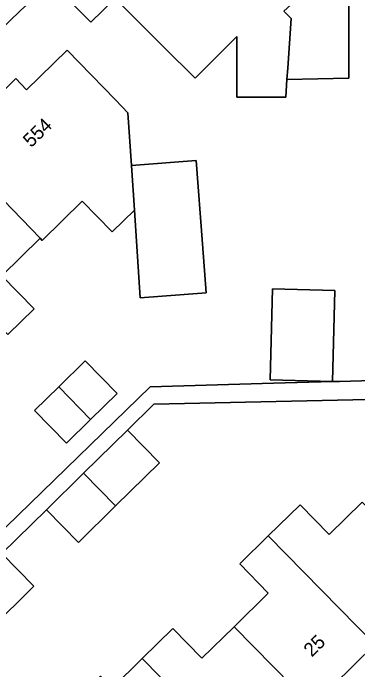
# Model space of a CAD drawing. Extents: x 162879 to 165540, y 384011 to 385181.
# Drawn here: x 164054.11 to 164079.05, y 384263.93 to 384311.42 of the extents above; entities that cross this region are included whole.
import ezdxf

# ---------------------------------------------------------------- set-up
doc = ezdxf.new("R2010")
doc.units = 0
for name, color, linetype in [('IMGEO_Erf', 7, 'Continuous'), ('IMGEO_Pand', 7, 'Continuous'), ('IMGEO_Pand_nummerreeks', 7, 'Continuous'), ('IMGEO_Voetpad_open', 7, 'Continuous')]:
    doc.layers.add(name, color=color, linetype=linetype)

msp = doc.modelspace()

# ---------------------------------------------------------------- linework, layer by layer
at = {"layer": 'IMGEO_Erf'}
for points in [[(164078.387, 384313.294), (164078.385, 384307.543), (164078.389, 384306.718), (164073.916, 384306.62), (164073.826, 384305.337), (164072.928, 384305.337), (164070.298, 384305.337), (164070.298, 384309.736), (164067.267, 384306.705), (164065.014, 384308.959), (164061.479, 384312.495), (164059.742, 384310.757), (164056.873, 384313.629)], [(164054.659, 384311.633), (164016.589, 384274.641), (164013.705, 384271.839), (164009.873, 384268.115), (164006.301, 384264.46), (164004.769, 384262.989), (164003.136, 384261.267), (164000.53, 384258.712), (164000.421, 384258.798), (164000, 384258.382), (163993.563, 384252.019), (163991.6, 384250), (163967.269, 384225.92)], [(164052.538, 384304.98), (164054.294, 384306.679), (164055.073, 384305.874), (164058.017, 384308.737), (164061.503, 384305.153), (164062.417, 384304.214), (164062.668, 384300.404), (164067.351, 384300.763), (164067.808, 384294.74), (164068.077, 384291.199), (164063.297, 384290.837), (164062.88, 384297.173), (164061.285, 384295.608), (164059.114, 384297.821), (164056.217, 384294.98), (164056.064, 384295.138), (164053.299, 384292.425), (164055.631, 384290.048), (164053.725, 384288.178)], [(164020.603, 384237.498), (164023.148, 384240.006), (164027.381, 384235.712), (164031.164, 384239.4), (164026.942, 384243.693), (164023.489, 384247.252), (164025.948, 384249.671), (164026.282, 384250), (164027.143, 384250.847), (164027.965, 384250), (164030.611, 384247.272), (164031.931, 384248.559), (164033.408, 384250), (164034.426, 384250.993), (164036.921, 384253.427), (164041.22, 384257.622), (164037.748, 384261.17), (164040.249, 384263.618), (164041.4, 384262.442), (164064.027, 384284.392), (164072.952, 384284.662), (164077.211, 384284.78), (164077.726, 384284.794), (164083.317, 384284.95)], [(164087.526, 384283.655), (164064.289, 384283.133), (164062.376, 384281.256), (164064.691, 384278.895), (164061.526, 384275.79), (164058.835, 384273.15), (164056.519, 384275.511), (164053.297, 384272.353), (164055.612, 384269.992), (164052.444, 384266.884), (164049.756, 384264.247), (164047.44, 384266.608), (164043.225, 384262.473)], [(164061.279, 384262.618), (164063.45, 384264.748), (164065.659, 384266.915), (164067.766, 384264.768), (164070.096, 384267.053), (164072.57, 384269.481), (164070.503, 384271.588), (164072.57, 384273.616), (164074.874, 384275.876), (164076.98, 384273.729), (164079.356, 384276.061)], [(164080.28, 384265.756), (164075.737, 384261.302), (164071.198, 384256.85), (164066.658, 384252.399), (164064.212, 384250), (164061.995, 384247.826), (164059.856, 384250), (164058.488, 384251.391), (164056.809, 384253.14), (164054.553, 384250.926), (164057.185, 384248.244), (164060.439, 384244.959)]]:
    msp.add_lwpolyline(points, dxfattribs=at)
for points in [[(164077.211, 384284.78), (164072.71, 384284.895), (164072.879, 384291.48), (164077.38, 384291.364)], [(164055.66, 384282.679), (164057.407, 384284.393), (164059.329, 384286.279), (164061.64, 384283.924), (164059.708, 384282.029), (164057.971, 384280.324)]]:
    msp.add_lwpolyline(points, close=True, dxfattribs=at)
at = {"layer": 'IMGEO_Pand'}
for points in [[(164078.147, 384322.503), (164075.109, 384322.449), (164075.088, 384322.341), (164068.094, 384318.642), (164070.557, 384315.972), (164073.763, 384312.495), (164074.196, 384312.026), (164073.696, 384311.565), (164074.227, 384311.037), (164073.974, 384307.446), (164073.916, 384306.62), (164078.389, 384306.718), (164078.385, 384307.543), (164078.387, 384313.294), (164078.404, 384314.042)], [(164073.696, 384311.565), (164074.196, 384312.026), (164073.763, 384312.495), (164070.557, 384315.972), (164069.94, 384315.354), (164068.609, 384314.022), (164065.831, 384316.8), (164061.479, 384312.495), (164065.014, 384308.959), (164067.267, 384306.705), (164070.298, 384309.736), (164070.298, 384305.337), (164072.928, 384305.337), (164073.826, 384305.337), (164073.916, 384306.62), (164073.974, 384307.446), (164074.227, 384311.037)], [(164062.417, 384304.214), (164061.503, 384305.153), (164058.017, 384308.737), (164055.073, 384305.874), (164054.294, 384306.679), (164052.538, 384304.98), (164053.169, 384304.345), (164050.068, 384301.337), (164056.064, 384295.138), (164056.217, 384294.98), (164059.114, 384297.821), (164061.285, 384295.608), (164062.88, 384297.173), (164062.668, 384300.404)], [(164050.068, 384301.337), (164049.966, 384301.238), (164050.119, 384301.08), (164045.521, 384296.61), (164053.725, 384288.178), (164055.631, 384290.048), (164053.299, 384292.425), (164056.064, 384295.138)], [(164067.351, 384300.763), (164062.668, 384300.404), (164062.88, 384297.173), (164063.297, 384290.837), (164068.077, 384291.199), (164067.808, 384294.74)], [(164077.211, 384284.78), (164077.38, 384291.364), (164072.879, 384291.48), (164072.71, 384284.895)], [(164057.407, 384284.393), (164059.708, 384282.029), (164061.64, 384283.924), (164059.329, 384286.279)], [(164057.407, 384284.393), (164055.66, 384282.679), (164057.971, 384280.324), (164059.708, 384282.029)], [(164061.526, 384275.79), (164064.691, 384278.895), (164062.376, 384281.256), (164059.21, 384278.151)], [(164061.526, 384275.79), (164059.21, 384278.151), (164056.519, 384275.511), (164058.835, 384273.15)], [(164080.28, 384265.756), (164084.962, 384270.347), (164081.46, 384273.916), (164079.356, 384276.061), (164076.98, 384273.729), (164074.874, 384275.876), (164072.57, 384273.616)], [(164080.28, 384265.756), (164072.57, 384273.616), (164070.503, 384271.588), (164072.57, 384269.481), (164070.096, 384267.053), (164075.737, 384261.302)], [(164052.444, 384266.884), (164055.612, 384269.992), (164053.297, 384272.353), (164050.128, 384269.244)], [(164070.096, 384267.053), (164067.766, 384264.768), (164065.659, 384266.915), (164063.45, 384264.748), (164071.198, 384256.85), (164075.737, 384261.302)], [(164063.45, 384264.748), (164061.279, 384262.618), (164060.428, 384263.485), (164058.06, 384261.162), (164058.911, 384260.295), (164061.027, 384258.138), (164066.658, 384252.399), (164071.198, 384256.85)]]:
    msp.add_lwpolyline(points, close=True, dxfattribs=at)
at = {"layer": 'IMGEO_Voetpad_open'}
msp.add_lwpolyline([(163967.269, 384225.92), (163991.6, 384250), (163993.563, 384252.019), (164000, 384258.382), (164000.421, 384258.798), (164000.53, 384258.712), (164003.136, 384261.267), (164004.769, 384262.989), (164006.301, 384264.46), (164009.873, 384268.115), (164013.705, 384271.839), (164016.589, 384274.641), (164054.659, 384311.633), (164056.143, 384312.967), (164056.873, 384313.629), (164059.742, 384310.757), (164061.479, 384312.495), (164065.831, 384316.8), (164067.159, 384318.159), (164068.094, 384318.642), (164075.088, 384322.341), (164075.109, 384322.449), (164073.319, 384326.088)], dxfattribs=at)
msp.add_lwpolyline([(164088.288, 384284.403), (164088.338, 384285.009), (164083.317, 384284.95), (164077.726, 384284.794), (164077.211, 384284.78), (164072.952, 384284.662), (164064.027, 384284.392), (164041.4, 384262.442), (164043.707, 384260.084), (164043.725, 384260.066), (164050.313, 384253.336), (164052.518, 384251.083), (164053.319, 384250.265), (164054.278, 384251.206), (164052.025, 384253.502), (164043.225, 384262.473), (164047.44, 384266.608), (164050.128, 384269.244), (164053.297, 384272.353), (164056.519, 384275.511), (164059.21, 384278.151), (164062.376, 384281.256), (164064.289, 384283.133), (164087.526, 384283.655)], close=True, dxfattribs=at)

# ---------------------------------------------------------------- texts
at = {"layer": 'IMGEO_Pand_nummerreeks'}
for s, rotation, p in [('554', 44.1922, (164055.412, 384301.651)), ('25', 44.4382, (164075.717, 384264.811))]:
    msp.add_text(s, height=1, rotation=rotation, dxfattribs=at).set_placement(p)

doc.saveas('drawing.dxf')
